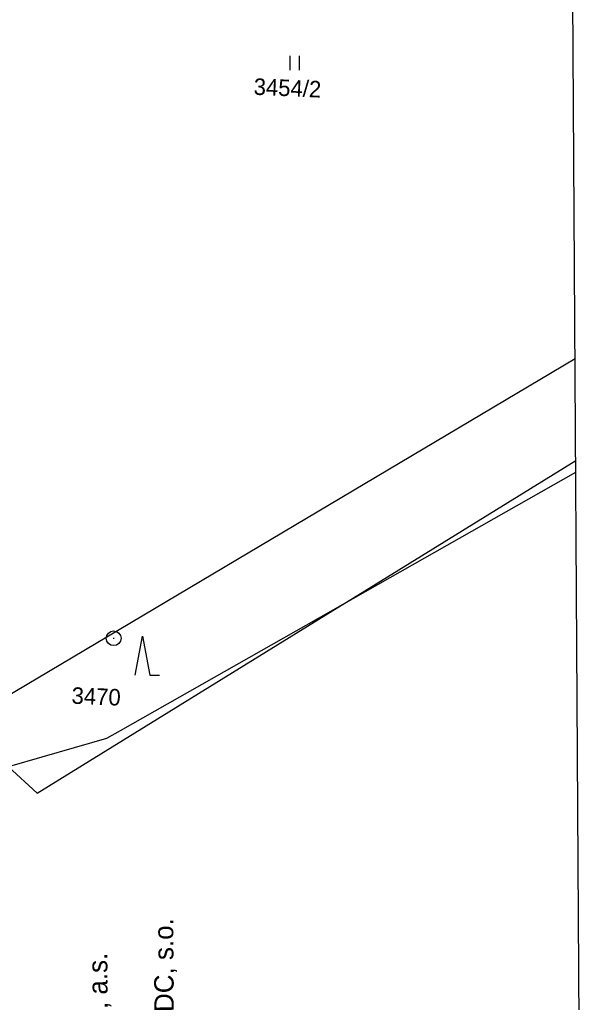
# Model space of a CAD drawing. Extents: x -735036 to -734743, y -1144813 to -1144181.
# Drawn here: x -734801.3 to -734743, y -1144707.5 to -1144606.3 of the extents above; entities that cross this region are included whole.
import ezdxf

# ---------------------------------------------------------------- set-up
doc = ezdxf.new("R2010")
doc.units = 0
for name, color, linetype in [('000_rozpiska', 7, 'Continuous'), ('BPEJ', 7, 'Continuous'), ('Katastr_Hranice parcel', 7, 'Continuous'), ('Katastr_Parcelní čísla', 7, 'Continuous'), ('Katastr_Značky kultur', 7, 'Continuous')]:
    doc.layers.add(name, color=color, linetype=linetype)

msp = doc.modelspace()

# ---------------------------------------------------------------- linework, layer by layer
at = {"layer": '000_rozpiska'}
msp.add_line((-734743.05, -1144810.64), (-734746.94, -1144180.65), dxfattribs=at)
at = {"layer": 'BPEJ'}
msp.add_lwpolyline([(-734802.5, -1144683.25), (-734799.5, -1144686), (-734768.16, -1144666.63), (-734768.09, -1144666.59), (-734744.03, -1144651.73)], dxfattribs=at)
at = {"layer": 'Defpoints'}
msp.add_line((-734743.05, -1144810.64), (-734745.64, -1144390.65), dxfattribs=at)
at = {"layer": 'Katastr_Hranice parcel'}
for points in [[(-734744.09, -1144641.26), (-734803.06, -1144676.31)], [(-734790.91, -1144679.53), (-734744.02, -1144652.95)], [(-734792.32, -1144680.32), (-734790.91, -1144679.53)], [(-734809.02, -1144685.13), (-734792.32, -1144680.32)]]:
    msp.add_lwpolyline(points, dxfattribs=at)
at = {"layer": 'Katastr_Značky kultur'}
for p, q in [((-734773.47, -1144610.06), (-734773.47, -1144611.56)), ((-734772.47, -1144611.56), (-734772.47, -1144610.06)), ((-734791.67, -1144670.04), (-734791.57, -1144670.04))]:
    msp.add_line(p, q, dxfattribs=at)
msp.add_lwpolyline([(-734789.41, -1144673.84), (-734788.66, -1144669.84), (-734787.91, -1144673.84), (-734786.91, -1144673.84)], dxfattribs=at)
msp.add_circle((-734791.62, -1144670.04), 0.756, dxfattribs=at)

# ---------------------------------------------------------------- texts
for s, p in [('DOTČENÉ NEMOVITOSTI VE VLASTNICTVÍ SŽDC, s.o.', (-734784.99, -1144767.21)), ('DOTČENÉ NEMOVITOSTI VE VLASTNICTVÍ ČD, a.s.', (-734791.8, -1144767.35))]:
    msp.add_text(s, height=2, rotation=90.4218).set_placement(p)
at = {"layer": 'Katastr_Parcelní čísla'}
for s, p in [('3454/2', (-734777.23, -1144614.08)), ('3470', (-734795.98, -1144676.77))]:
    msp.add_text(s, height=1.7, rotation=357.5604, dxfattribs=at).set_placement(p)

doc.saveas('drawing.dxf')
